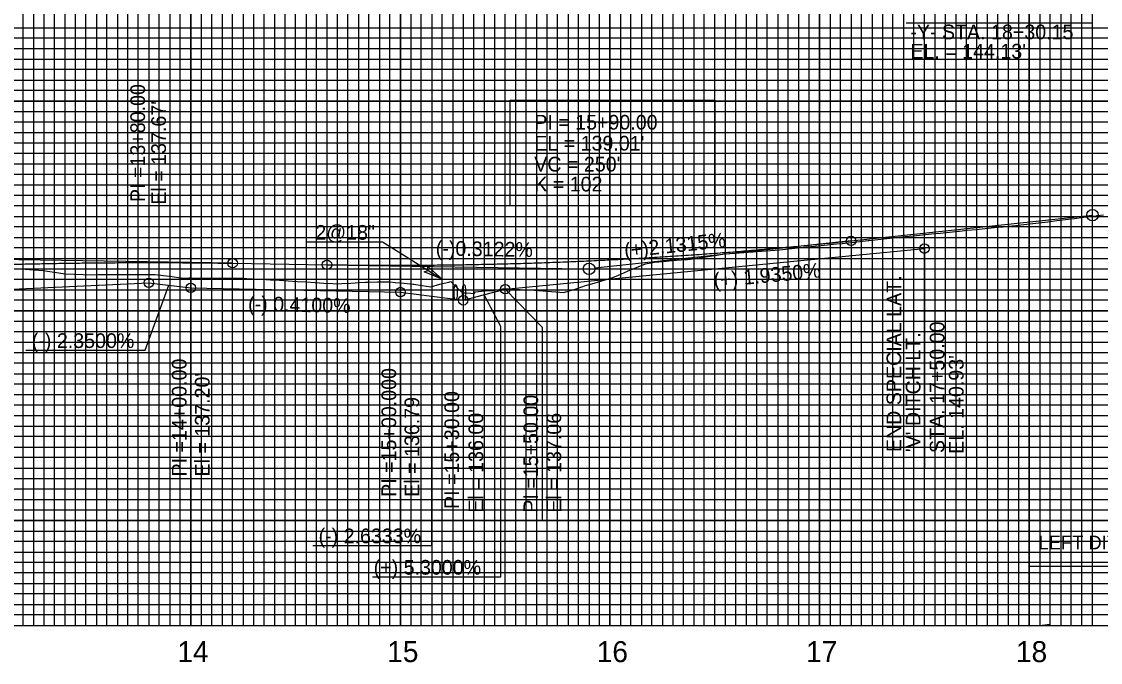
# Model space of a CAD drawing. Extents: x 573468 to 580768, y -57414 to -51768.
# Drawn here: x 579215 to 579729, y -54656 to -54351 of the extents above; entities that cross this region are included whole.
import ezdxf

# ---------------------------------------------------------------- set-up
doc = ezdxf.new("R2010")
doc.units = 0
for name, color, linetype in [('Exist Vertical Profile Ground Line', 7, 'Continuous'), ('Exist Vertical Profile Horizontal Axis Label Major', 7, 'Continuous'), ('Prop Approach Slab Hatching', 7, 'Continuous'), ('Prop Grid Mask', 7, 'Continuous'), ('Prop PFL Cross Pipe Text CELL', 7, 'Continuous'), ('Prop PFL Ditch Label CELL', 7, 'Continuous'), ('Prop PFL Text', 7, 'Continuous'), ('Prop Terminator CELL', 7, 'Continuous'), ('Prop Vertical Profile Curve Label', 7, 'Continuous'), ('Prop Vertical Profile Ditch Grade Left', 7, 'Continuous'), ('Prop Vertical Profile Ditch Grade Left Label', 7, 'Continuous'), ('Prop Vertical Profile Grade', 7, 'Continuous'), ('Prop Vertical Profile Grade Label', 7, 'Continuous'), ('Prop VPI Ditch Grade Left Label', 7, 'Continuous'), ('Prop VPI Label', 7, 'Continuous'), ('Sheet DOT Grid CELL', 7, 'Continuous'), ('Sheet Layout Profile Border Port 1', 7, 'Continuous'), ('Sheet Profile CELL', 7, 'Continuous'), ('Sheet Profile Grid Major CELL', 7, 'Continuous'), ('Sheet Profile Grid Middle CELL', 7, 'Continuous'), ('Sheet Profile Grid Minor CELL', 7, 'Continuous')]:
    doc.layers.add(name, color=color, linetype=linetype)

# ---------------------------------------------------------------- blocks, each defined once
blk = doc.blocks.new('Ditch Label Left')
at = {"layer": 'Prop Grid Mask'}
blk.add_lwpolyline([(-75, 12.5), (75, 12.5), (75, -12.5), (-75, -12.5)], close=True, dxfattribs=at)
at = {"layer": 'Prop PFL Ditch Label CELL'}
blk.add_line((10.55, 0.2), (70.55, 0.2), dxfattribs=at)
blk.add_text('LEFT DITCH', height=7.485, dxfattribs=at).set_placement((-70, -3.2))

msp = doc.modelspace()

# ---------------------------------------------------------------- linework, layer by layer
at = {"layer": 'Exist Vertical Profile Ground Line'}
for points in [[(579524.9, -54464.63), (579529.17, -54464.3), (579532.11, -54464.07), (579533.43, -54463.87), (579537.7, -54463.23), (579541.96, -54462.6), (579546.23, -54461.97), (579549.87, -54461.42), (579550.49, -54461.37), (579554.76, -54461.04), (579559.02, -54460.71), (579563.29, -54460.38), (579567.55, -54460.06), (579571.82, -54459.73), (579576.08, -54459.4), (579580.35, -54458.96), (579584.61, -54458.51), (579588.88, -54458.09), (579593.14, -54457.66), (579597.41, -54457.24), (579601.67, -54456.82), (579603.26, -54456.66), (579605.94, -54456.38), (579610.2, -54455.93), (579614.47, -54455.48), (579618.36, -54455.08), (579618.73, -54455.03), (579623, -54454.55), (579627.26, -54454.06), (579630.19, -54453.73), (579631.53, -54453.6), (579635.79, -54453.17), (579640.06, -54452.74), (579644.32, -54452.32), (579648.59, -54451.89), (579652.85, -54451.47), (579654.13, -54451.34), (579657.12, -54451.02), (579661.38, -54450.56), (579661.87, -54450.51), (579665.65, -54450.14), (579669.91, -54449.72), (579674.18, -54449.31), (579678.45, -54448.89), (579682.71, -54448.48), (579686.98, -54448.06), (579690.61, -54447.71), (579691.24, -54447.63), (579695.51, -54447.11), (579699.77, -54446.58), (579704.04, -54446.06), (579708.3, -54445.54), (579712.57, -54445.01), (579716.83, -54444.49), (579721.1, -54443.97), (579725.36, -54443.44), (579727.3, -54443.21), (579727.69, -54443.16), (579730.56, -54442.74)], [(579243.89, -54471.16), (579248.14, -54471.32), (579251, -54471.28), (579252.4, -54471.27), (579256.65, -54471.26), (579260.91, -54471.25), (579265.16, -54471.24), (579269.42, -54471.23), (579271.12, -54471.22), (579273.67, -54471.23), (579277.92, -54471.24), (579278.25, -54471.25), (579282.18, -54471.73), (579286.43, -54472.26), (579290.32, -54472.75), (579290.69, -54472.79), (579292.85, -54473.04), (579294.36, -54472.78), (579294.94, -54472.8), (579299.2, -54472.96), (579300.8, -54473.02), (579303.45, -54473), (579307.7, -54472.98), (579311.96, -54472.95), (579316.21, -54472.92), (579317.95, -54472.91), (579320.47, -54473.05), (579321.9, -54473.13), (579324.72, -54473.26), (579328.21, -54473.41), (579328.98, -54473.46), (579333.23, -54473.73), (579337.48, -54474.01), (579341.74, -54474.28), (579345.99, -54474.53), (579350.25, -54474.79), (579354.5, -54475.04), (579358.76, -54475.29), (579363.01, -54475.55), (579365.36, -54475.69), (579367.26, -54475.58), (579371.52, -54475.32), (579375.77, -54475.07), (579378.47, -54474.91), (579380.19, -54474.89), (579384.28, -54474.78), (579387.49, -54474.7), (579388.54, -54474.71), (579388.89, -54474.72), (579390.35, -54474.79), (579392.79, -54475.02), (579397.04, -54475.42), (579401.3, -54475.82), (579401.6, -54475.85), (579405.55, -54476.44), (579409.81, -54477.05), (579414.06, -54475.82), (579415.29, -54475.47), (579418.32, -54474.85), (579419.34, -54474.64), (579421.32, -54476.71), (579422.57, -54477.87), (579424.78, -54479.92), (579426.82, -54480.05), (579428.75, -54480.16), (579430.35, -54480.35), (579431.08, -54479.47), (579435.33, -54478.95), (579436.4, -54478.81), (579437.25, -54478.91), (579439.02, -54478.95), (579439.6, -54478.84), (579443.86, -54478.05), (579444.63, -54477.91), (579448.13, -54478.09), (579452.39, -54478.31), (579456.66, -54478.51), (579457.32, -54478.54), (579460.92, -54478.85), (579465.19, -54479.21), (579469.45, -54479.56), (579473.21, -54479.86), (579473.72, -54479.71), (579477.55, -54478.62), (579478.17, -54478.36), (579482.25, -54476.94), (579483, -54476.68), (579484.1, -54476.33), (579486.51, -54475.62), (579490.78, -54474.39), (579495.04, -54473.18), (579495.8, -54472.97), (579499.31, -54471.48), (579503.57, -54469.69), (579507.84, -54467.91), (579512.17, -54466.12), (579516.37, -54465.43), (579517.83, -54465.18), (579518.44, -54465.13), (579520.63, -54464.96), (579524.9, -54464.63)], [(579214.11, -54468.59), (579218.36, -54468.89), (579222.62, -54469.2), (579224.86, -54469.36), (579226.87, -54469.66), (579231.13, -54470.3), (579234.41, -54470.8), (579235.38, -54470.84), (579239.64, -54471), (579243.89, -54471.16)]]:
    msp.add_lwpolyline(points, dxfattribs=at)
at = {"layer": 'Prop Grid Mask'}
msp.add_lwpolyline([(579447.59, -54388.13), (579545.21, -54388.13), (579545.21, -54438.55), (579447.59, -54438.55)], close=True, dxfattribs=at)
at = {"layer": 'Prop PFL Cross Pipe Text CELL'}
for p, q in [((579350.31, -54455.7), (579386.75, -54455.7)), ((579386.75, -54455.7), (579415.1, -54473.49))]:
    msp.add_line(p, q, dxfattribs=at)
for centre in [(579421.6, -54479.8), (579425.6, -54479.8)]:
    msp.add_ellipse(centre, major_axis=(0, 3.75), ratio=0.2, dxfattribs=at)
at = {"layer": 'Prop PFL Text'}
for p in [(579636.44, -54351.28), (579725.36, -54440.17)]:
    msp.add_line(p, (579725.36, -54351.28), dxfattribs=at)
at = {"layer": 'Prop Terminator CELL'}
msp.add_lwpolyline([(579408.3, -54467.39), (579415.1, -54473.49), (579406.58, -54470.03), (579408.41, -54469.29)], close=True, dxfattribs=at)
at = {"layer": 'Prop Vertical Profile Curve Label'}
for centre in [(579610.21, -54455.19), (579315.21, -54465.86), (579360.21, -54466.57)]:
    msp.add_circle(centre, 2.25, dxfattribs=at)
at = {"layer": 'Prop Vertical Profile Ditch Grade Left'}
msp.add_line((578910.21, -54491.95), (579275.21, -54475.2), dxfattribs=at)
for points in [[(579425.21, -54483.55), (579445.21, -54478.25), (579645.21, -54458.9)], [(579275.21, -54475.2), (579295.21, -54477.55), (579395.21, -54479.6), (579425.21, -54483.55)]]:
    msp.add_lwpolyline(points, dxfattribs=at)
at = {"layer": 'Prop Vertical Profile Ditch Grade Left Label'}
for p, q in [((579275.21, -54364.47), (579275.21, -54475.2)), ((579645.21, -54458.9), (579645.21, -54563.78)), ((579273.41, -54507.31), (579284.78, -54476.32)), ((579295.21, -54477.55), (579295.21, -54573.55)), ((579395.21, -54479.6), (579395.21, -54584.48)), ((579462.79, -54496.3), (579445.21, -54478.25)), ((579410.21, -54600.42), (579410.21, -54481.57)), ((579425.21, -54483.55), (579425.21, -54588.43)), ((579443.07, -54496.06), (579435.21, -54480.9)), ((579443.07, -54615.39), (579443.07, -54496.06)), ((579462.79, -54496.3), (579462.79, -54588.43)), ((579216.6, -54507.31), (579273.41, -54507.31)), ((579353.41, -54600.42), (579410.21, -54600.42)), ((579381.96, -54615.39), (579443.07, -54615.39))]:
    msp.add_line(p, q, dxfattribs=at)
for centre in [(579645.21, -54458.9), (579275.21, -54475.2), (579295.21, -54477.55), (579395.21, -54479.6), (579445.21, -54478.25), (579425.21, -54483.55)]:
    msp.add_circle(centre, 2.25, dxfattribs=at)
at = {"layer": 'Prop Vertical Profile Grade'}
for p, q in [((579610.21, -54455.19), (579725.36, -54442.92)), ((579315.21, -54465.86), (579360.21, -54466.57))]:
    msp.add_line(p, q, dxfattribs=at)
for points in [[(579360.21, -54466.57), (579365.21, -54466.64), (579370.21, -54466.7), (579375.21, -54466.74), (579380.21, -54466.78), (579385.21, -54466.8), (579390.21, -54466.81), (579395.21, -54466.81), (579400.21, -54466.8), (579405.21, -54466.77), (579410.21, -54466.73), (579415.21, -54466.68), (579420.21, -54466.62), (579425.21, -54466.55), (579430.21, -54466.46), (579435.21, -54466.36), (579440.21, -54466.25), (579445.21, -54466.13), (579450.21, -54465.99), (579455.21, -54465.84), (579460.21, -54465.68), (579465.21, -54465.51), (579470.21, -54465.33), (579475.21, -54465.13), (579480.21, -54464.92), (579485.21, -54464.7), (579490.21, -54464.46), (579495.21, -54464.22), (579500.21, -54463.96), (579505.21, -54463.69), (579510.21, -54463.41), (579515.21, -54463.11), (579520.21, -54462.81), (579525.21, -54462.49), (579530.21, -54462.16), (579535.21, -54461.81), (579540.21, -54461.46), (579545.21, -54461.09), (579550.21, -54460.71), (579555.21, -54460.32), (579560.21, -54459.91), (579565.21, -54459.5), (579570.21, -54459.07), (579575.21, -54458.62), (579580.21, -54458.17), (579585.21, -54457.71), (579590.21, -54457.23), (579595.21, -54456.74), (579600.21, -54456.24), (579605.21, -54455.72), (579610.21, -54455.19)], [(578915.21, -54490.73), (578923.21, -54489.63), (578931.21, -54488.54), (578939.21, -54487.49), (578947.21, -54486.45), (578955.21, -54485.45), (578963.21, -54484.46), (578971.21, -54483.51), (578979.21, -54482.57), (578987.21, -54481.66), (578995.21, -54480.78), (579003.21, -54479.92), (579011.21, -54479.09), (579019.21, -54478.28), (579027.21, -54477.5), (579035.21, -54476.74), (579043.21, -54476), (579051.21, -54475.3), (579059.21, -54474.61), (579067.21, -54473.95), (579075.21, -54473.32), (579083.21, -54472.71), (579091.21, -54472.12), (579099.21, -54471.56), (579107.21, -54471.03), (579115.21, -54470.52), (579123.21, -54470.03), (579131.21, -54469.57), (579139.21, -54469.14), (579147.21, -54468.73), (579155.21, -54468.34), (579163.21, -54467.98), (579171.21, -54467.65), (579179.21, -54467.34), (579187.21, -54467.05), (579195.21, -54466.79), (579203.21, -54466.55), (579211.21, -54466.34), (579219.21, -54466.16), (579227.21, -54465.99), (579235.21, -54465.86), (579243.21, -54465.75), (579251.21, -54465.66), (579259.21, -54465.6), (579267.21, -54465.56), (579275.21, -54465.55), (579283.21, -54465.56), (579291.21, -54465.6), (579299.21, -54465.66), (579307.21, -54465.75), (579315.21, -54465.86)]]:
    msp.add_spline(points, degree=3, dxfattribs=at)
at = {"layer": 'Prop VPI Label'}
for p, q in [((579610.21, -54455.19), (579487.95, -54468.22)), ((579315.21, -54465.86), (579117.96, -54462.78)), ((579360.21, -54466.57), (579482.47, -54468.47))]:
    msp.add_line(p, q, dxfattribs=at)
for centre in [(579725.36, -54442.92), (579485.21, -54468.52)]:
    msp.add_circle(centre, 2.75, dxfattribs=at)
at = {"layer": 'Sheet DOT Grid CELL'}
for p, q in [((579245.21, -54638.55), (579245.21, -54138.55)), ((579295.21, -54638.55), (579295.21, -54138.55)), ((579345.21, -54638.55), (579345.21, -54138.55)), ((579395.21, -54638.55), (579395.21, -54138.55)), ((579445.21, -54638.55), (579445.21, -54138.55)), ((579495.21, -54638.55), (579495.21, -54138.55)), ((579545.21, -54638.55), (579545.21, -54138.55)), ((579595.21, -54638.55), (579595.21, -54138.55)), ((579645.21, -54638.55), (579645.21, -54138.55)), ((579695.21, -54638.55), (579695.21, -54138.55)), ((580345.21, -54388.55), (578845.21, -54388.55)), ((580345.21, -54438.55), (578845.21, -54438.55)), ((580345.21, -54488.55), (578845.21, -54488.55)), ((580345.21, -54538.55), (578845.21, -54538.55)), ((580345.21, -54588.55), (578845.21, -54588.55))]:
    msp.add_line(p, q, dxfattribs=at)
at = {"layer": 'Sheet Layout Profile Border Port 1'}
msp.add_lwpolyline([(578895.21, -54138.55), (578895.21, -54638.55), (580295.21, -54638.55), (580295.21, -54276.1), (580145.16, -54276.1), (580145.16, -54138.55)], close=True, dxfattribs=at)
at = {"layer": 'Sheet Profile CELL'}
msp.add_line((578845.21, -54638.55), (580345.21, -54638.55), dxfattribs=at)
at = {"layer": 'Sheet Profile Grid Major CELL'}
for points in [[(579195.21, -54638.55), (579245.21, -54638.55), (579245.21, -54138.55), (579295.21, -54138.55), (579295.21, -54638.55), (579345.21, -54638.55), (579345.21, -54138.55), (579395.21, -54138.55), (579395.21, -54638.55), (579445.21, -54638.55), (579445.21, -54138.55), (579495.21, -54138.55), (579495.21, -54638.55), (579545.21, -54638.55), (579545.21, -54138.55), (579595.21, -54138.55), (579595.21, -54638.55), (579645.21, -54638.55), (579645.21, -54138.55), (579695.21, -54138.55), (579695.21, -54638.55), (579745.21, -54638.55)], [(580345.21, -54338.55), (578845.21, -54338.55), (578845.21, -54388.55), (580345.21, -54388.55)], [(580345.21, -54438.55), (578845.21, -54438.55), (578845.21, -54488.55), (580345.21, -54488.55)], [(580345.21, -54538.55), (578845.21, -54538.55), (578845.21, -54538.55), (578845.21, -54588.55), (580345.21, -54588.55)]]:
    msp.add_lwpolyline(points, dxfattribs=at)
at = {"layer": 'Sheet Profile Grid Middle CELL'}
for points in [[(579220.21, -54138.55), (579220.21, -54638.55), (579270.21, -54638.55), (579270.21, -54138.55)], [(579320.21, -54138.55), (579320.21, -54638.55), (579370.21, -54638.55), (579370.21, -54138.55)], [(579420.21, -54138.55), (579420.21, -54638.55), (579470.21, -54638.55), (579470.21, -54638.55), (579470.21, -54138.55)], [(579520.21, -54138.55), (579520.21, -54638.55), (579570.21, -54638.55), (579570.21, -54138.55)], [(579620.21, -54138.55), (579620.21, -54638.55), (579670.21, -54638.55), (579670.21, -54138.55)], [(579720.21, -54138.55), (579720.21, -54638.55), (579770.21, -54638.55)], [(580345.21, -54313.55), (578845.21, -54313.55), (578845.21, -54363.55), (580170.21, -54363.55)], [(580345.21, -54413.55), (578845.21, -54413.55), (578845.21, -54463.55), (580345.21, -54463.55)], [(580345.21, -54513.55), (578845.21, -54513.55), (578845.21, -54563.55), (580345.21, -54563.55)], [(580345.21, -54613.55), (578845.21, -54613.55)]]:
    msp.add_lwpolyline(points, dxfattribs=at)
at = {"layer": 'Sheet Profile Grid Minor CELL'}
for p, q in [((578895.21, -54353.55), (580295.21, -54353.55)), ((580295.21, -54373.55), (578895.21, -54373.55)), ((578895.21, -54378.55), (580295.21, -54378.55)), ((580295.21, -54383.55), (578895.21, -54383.55)), ((578895.21, -54393.55), (580295.21, -54393.55)), ((580295.21, -54398.55), (578895.21, -54398.55)), ((578895.21, -54403.55), (580295.21, -54403.55)), ((580295.21, -54408.55), (578895.21, -54408.55)), ((578895.21, -54418.55), (580295.21, -54418.55)), ((580295.21, -54423.55), (578895.21, -54423.55)), ((578895.21, -54428.55), (580295.21, -54428.55)), ((580295.21, -54433.55), (578895.21, -54433.55)), ((578895.21, -54443.55), (580295.21, -54443.55)), ((580295.21, -54448.55), (578895.21, -54448.55)), ((578895.21, -54453.55), (580295.21, -54453.55)), ((580295.21, -54458.55), (578895.21, -54458.55)), ((578895.21, -54468.55), (580295.21, -54468.55)), ((580295.21, -54473.55), (578895.21, -54473.55)), ((578895.21, -54478.55), (580295.21, -54478.55)), ((580295.21, -54483.55), (578895.21, -54483.55)), ((578895.21, -54493.55), (580295.21, -54493.55)), ((580295.21, -54498.55), (578895.21, -54498.55)), ((578895.21, -54503.55), (580295.21, -54503.55)), ((580295.21, -54508.55), (578895.21, -54508.55)), ((578895.21, -54518.55), (580295.21, -54518.55)), ((580295.21, -54523.55), (578895.21, -54523.55)), ((580295.21, -54528.55), (578895.21, -54528.55)), ((580295.21, -54533.55), (578895.21, -54533.55)), ((578895.21, -54543.55), (580295.21, -54543.55)), ((580295.21, -54548.55), (578895.21, -54548.55)), ((578895.21, -54553.55), (580295.21, -54553.55)), ((580295.21, -54558.55), (578895.21, -54558.55)), ((578895.21, -54568.55), (580295.21, -54568.55)), ((580295.21, -54573.55), (578895.21, -54573.55)), ((578895.21, -54578.55), (580295.21, -54578.55)), ((580295.21, -54583.55), (578895.21, -54583.55)), ((578895.21, -54593.55), (580295.21, -54593.55)), ((580295.21, -54598.55), (578895.21, -54598.55)), ((578895.21, -54603.55), (580295.21, -54603.55)), ((580295.21, -54608.55), (578895.21, -54608.55)), ((578895.21, -54618.55), (580295.21, -54618.55)), ((580295.21, -54623.55), (578895.21, -54623.55)), ((578895.21, -54628.55), (580295.21, -54628.55))]:
    msp.add_line(p, q, dxfattribs=at)
for points in [[(579210.21, -54638.55), (579215.21, -54638.55), (579215.21, -54138.55)], [(579225.21, -54138.55), (579225.21, -54638.55), (579230.21, -54638.55), (579230.21, -54138.55)], [(579235.21, -54138.55), (579235.21, -54638.55), (579240.21, -54638.55), (579240.21, -54138.55)], [(579250.21, -54138.55), (579250.21, -54638.55), (579255.21, -54638.55), (579255.21, -54138.55)], [(579260.21, -54138.55), (579260.21, -54638.55), (579265.21, -54638.55), (579265.21, -54138.55)], [(579275.21, -54138.55), (579275.21, -54638.55), (579280.21, -54638.55), (579280.21, -54138.55)], [(579285.21, -54138.55), (579285.21, -54638.55), (579290.21, -54638.55), (579290.21, -54138.55)], [(579300.21, -54138.55), (579300.21, -54638.55), (579305.21, -54638.55), (579305.21, -54138.55)], [(579310.21, -54138.55), (579310.21, -54638.55), (579315.21, -54638.55), (579315.21, -54138.55)], [(579325.21, -54138.55), (579325.21, -54638.55), (579330.21, -54638.55), (579330.21, -54138.55)], [(579335.21, -54138.55), (579335.21, -54638.55), (579340.21, -54638.55), (579340.21, -54138.55)], [(579350.21, -54138.55), (579350.21, -54638.55), (579355.21, -54638.55), (579355.21, -54138.55)], [(579360.21, -54138.55), (579360.21, -54638.55), (579365.21, -54638.55), (579365.21, -54138.55)], [(579375.21, -54138.55), (579375.21, -54638.55), (579380.21, -54638.55), (579380.21, -54138.55)], [(579385.21, -54138.55), (579385.21, -54638.55), (579390.21, -54638.55), (579390.21, -54138.55)], [(579400.21, -54138.55), (579400.21, -54638.55), (579405.21, -54638.55), (579405.21, -54138.55)], [(579410.21, -54138.55), (579410.21, -54638.55), (579415.21, -54638.55), (579415.21, -54138.55)], [(579425.21, -54138.55), (579425.21, -54638.55), (579430.21, -54638.55), (579430.21, -54138.55)], [(579435.21, -54138.55), (579435.21, -54638.55), (579440.21, -54638.55), (579440.21, -54138.55)], [(579450.21, -54138.55), (579450.21, -54638.55), (579455.21, -54638.55), (579455.21, -54138.55)], [(579460.21, -54138.55), (579460.21, -54638.55), (579465.21, -54638.55), (579465.21, -54138.55)], [(579475.21, -54138.55), (579475.21, -54638.55), (579480.21, -54638.55), (579480.21, -54138.55)], [(579485.21, -54138.55), (579485.21, -54638.55), (579490.21, -54638.55), (579490.21, -54138.55)], [(579500.21, -54138.55), (579500.21, -54638.55), (579505.21, -54638.55), (579505.21, -54138.55)], [(579510.21, -54138.55), (579510.21, -54638.55), (579515.21, -54638.55), (579515.21, -54138.55)], [(579525.21, -54138.55), (579525.21, -54638.55), (579530.21, -54638.55), (579530.21, -54138.55)], [(579535.21, -54138.55), (579535.21, -54638.55), (579540.21, -54638.55), (579540.21, -54138.55)], [(579550.21, -54138.55), (579550.21, -54638.55), (579550.21, -54638.55), (579555.21, -54638.55), (579555.21, -54138.55)], [(579560.21, -54138.55), (579560.21, -54638.55), (579565.21, -54638.55), (579565.21, -54138.55)], [(579575.21, -54138.55), (579575.21, -54638.55), (579580.21, -54638.55), (579580.21, -54138.55)], [(579585.21, -54138.55), (579585.21, -54638.55), (579590.21, -54638.55), (579590.21, -54138.55)], [(579600.21, -54138.55), (579600.21, -54638.55), (579605.21, -54638.55), (579605.21, -54138.55)], [(579610.21, -54138.55), (579610.21, -54638.55), (579615.21, -54638.55), (579615.21, -54138.55)], [(579625.21, -54138.55), (579625.21, -54638.55), (579630.21, -54638.55), (579630.21, -54138.55)], [(579635.21, -54138.55), (579635.21, -54638.55), (579640.21, -54638.55), (579640.21, -54138.55)], [(579650.21, -54138.55), (579650.21, -54638.55), (579655.21, -54638.55), (579655.21, -54138.55)], [(579660.21, -54138.55), (579660.21, -54638.55), (579665.21, -54638.55), (579665.21, -54138.55)], [(579675.21, -54138.55), (579675.21, -54638.55), (579680.21, -54638.55), (579680.21, -54138.55)], [(579685.21, -54138.55), (579685.21, -54638.55), (579690.21, -54638.55), (579690.21, -54138.55)], [(579700.21, -54138.55), (579700.21, -54638.55), (579704.91, -54638), (579705.21, -54638.55), (579705.21, -54138.55)], [(579710.21, -54138.55), (579710.21, -54638.55), (579715.21, -54638.55), (579715.21, -54138.55)], [(579725.21, -54138.55), (579725.21, -54638.55), (579730.21, -54638.55)], [(580295.21, -54358.55), (578895.21, -54358.55), (578895.21, -54368.55), (580295.21, -54368.55)], [(580295.21, -54633.55), (578895.21, -54633.55)]]:
    msp.add_lwpolyline(points, dxfattribs=at)

# ---------------------------------------------------------------- block references
at = {"layer": 'Prop Approach Slab Hatching', "xscale": 0.875, "yscale": 0.875}
msp.add_blockref('Ditch Label Left', (579760.84, -54599.49), dxfattribs=at)

# ---------------------------------------------------------------- texts
at = {"layer": 'Exist Vertical Profile Horizontal Axis Label Major'}
for s, p in [('14', (579288.86, -54656.05)), ('15', (579388.96, -54656.05)), ('16', (579488.9, -54656.05)), ('17', (579588.75, -54656.05)), ('18', (579688.88, -54656.05))]:
    msp.add_text(s, height=10, dxfattribs=at).set_placement(p)
at = {"layer": 'Prop PFL Cross Pipe Text CELL'}
msp.add_text('2@18"', height=7, rotation=360, dxfattribs=at).set_placement((579354.63, -54454.65))
at = {"layer": 'Prop PFL Text'}
for s, p in [('-Y- STA. 18+30.15', (579638.5, -54359.09)), ("EL. = 144.13'", (579638.5, -54368.27))]:
    msp.add_text(s, height=7, dxfattribs=at).set_placement(p)
at = {"layer": 'Prop Vertical Profile Curve Label'}
for s, p in [("VC = 250'", (579459.09, -54422.13)), ('K = 102', (579459.09, -54431.64))]:
    msp.add_text(s, height=7, dxfattribs=at).set_placement(p)
at = {"layer": 'Prop Vertical Profile Ditch Grade Left'}
for s, rotation, p in [('PI =13+80.00', 90, (579273.4, -54436.67)), ("El = 137.67'", 90, (579283.39, -54437.95)), ('(+) 1.9350%', 5.53, (579544.94, -54477.54)), ('(-) 0.4100%', 358.8322, (579322.52, -54488.61)), ('(-) 2.3500%', 360, (579219.4, -54506.27)), ("EL. 140.93'", 90, (579663.89, -54556.74)), ('PI =14+00.00', 90, (579293.21, -54567.55)), ("El = 137.20'", 90, (579304.21, -54567.55)), ('PI =15+30.00', 90, (579423.22, -54583.04)), ("El = 136.00'", 90, (579434.73, -54584.79)), ('(-) 2.6333%', 360, (579356.2, -54599.37)), ('(+) 5.3000%', 360, (579382.47, -54614.35))]:
    msp.add_text(s, height=7, rotation=rotation, dxfattribs=at).set_placement(p)
at = {"layer": 'Prop Vertical Profile Ditch Grade Left Label'}
for s, p in [('END SPECIAL LAT. ', (579634.13, -54555.92)), ('STA. 17+50.00', (579654.74, -54556.36)), ("'V' DITCH LT. ", (579643.31, -54555.92))]:
    msp.add_text(s, height=7, rotation=90, dxfattribs=at).set_placement(p)
at = {"layer": 'Prop Vertical Profile Grade Label'}
for s, rotation, p in [('(-)0.3122%', 359.1058, (579412.06, -54462.16)), ('(+)2.1315%', 6.0835, (579502.35, -54463.28))]:
    msp.add_text(s, height=7, rotation=rotation, dxfattribs=at).set_placement(p)
at = {"layer": 'Prop VPI Ditch Grade Left Label'}
for s, p in [('PI =15+00.000', (579393.21, -54577.25)), ('El = 136.79', (579404.21, -54577.25)), ('PI =15+50.00', (579460.94, -54584.81)), ('El = 137.06', (579471.94, -54584.81))]:
    msp.add_text(s, height=7, rotation=90, dxfattribs=at).set_placement(p)
at = {"layer": 'Prop VPI Label'}
for s, p in [('PI = 15+90.00', (579459.09, -54402.13)), ("EL = 139.01'", (579459.09, -54412.13))]:
    msp.add_text(s, height=7, dxfattribs=at).set_placement(p)

doc.saveas('drawing.dxf')
